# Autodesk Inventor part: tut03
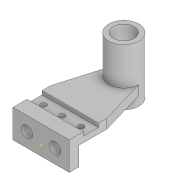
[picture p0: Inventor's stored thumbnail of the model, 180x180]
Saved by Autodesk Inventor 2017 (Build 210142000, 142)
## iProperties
Created: 2015-03
Part Number: tut03
Material: Generic
Document SubType Name: Modeling
Designer: Sandeep
Density: 1 g/cm^3
Appearance: Default
Author: Sandeep
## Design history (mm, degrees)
sketch "Sketch1"
  geometry: L1 (0, 0)-(10, 0); L2 (10, 0)-(10, 20); L3 (10, 20)-(40, 20); L4 (40, 20)-(40, 30); L5 (40, 30)-(31, 30); L6 (31, 30)-(31, 26); L7 (31, 26)-(15, 26); L8 (15, 26)-(15, 30); L9 (15, 30)-(0, 30); L10 (0, 30)-(0, 0)
  constraints: 20 end point, 7 perpendicular, 1 collinear, 1 horizontal, 1 parallel, 1 vertical
  dimensions: "d0" = 10 distance of L1.start L1.end; "d1" = 30 distance of L9.end L1.start; "d2" = 4 distance between parallel lines of L9 L7; "d3" = 15 distance of L8.end L9.end; "d4" = 16 distance of L6.end L7.end; "d5" = 40 distance between parallel lines of L4 L10; "d6" = 10 distance between parallel lines of L5 L3
extrude "Extrusion1" new body sketch "Sketch1" stored distance "d7" = 60; taper "d8" = 0 deg
sketch "Sketch2"
  geometry: L1 (0, 40)-(14, 88); L2 (14, 88)-(46, 88); L3 (0, 40)-(60, 40) reference; L4 (46, 88)-(60, 40); L5 (60, 40)-(0, 40); L6 (30, 0)-(30, 52.82)
  constraints: 11 end point, 1 horizontal, 1 vertical, 1 other
  dimensions: "d9" = 48 distance between parallel lines of L3 L2; "d10" = 32 distance of L1.end L2.end
extrude "Extrusion2" join sketch "Sketch2" distance "d11" = 10; taper "d12" = 0 deg
workplane "Work Plane1"
sketch "Sketch3"
  geometry: 1 further point
sketch "Sketch4"
  geometry: L1 (46, 78)-(14, 78) reference; C1 r 16 at (30, 78); 1 further point
  constraints: 1 centre point, 1 midpoint
  dimensions: "d14" = 32 diameter of C1
extrude "Extrusion3" join sketch "Sketch4" distance "d15" = 60; taper "d16" = 0 deg
sketch "Sketch5"
  geometry: C1 r 11 at (0, 0); C2 r 16 at (0, 0) reference; 1 further point
  constraints: 1 centre point, 1 concentric
  dimensions: "d17" = 22 diameter of C1
extrude "Extrusion4" cut sketch "Sketch5" stored distance "d18" = 0; taper "d19" = 0 deg
sketch "Sketch6"
  geometry: L1 (0.322, 7.5)-(90.552, 7.5); L2 (0, -15)-(60, -15) reference; L3 (0, 0)-(0, 16) reference; C1 r 3 at (10, 7.5); C2 r 3 at (30, 7.5); C3 r 3 at (50, 7.5); 1 further point
  constraints: 3 centre point, 3 point on line, 2 end point, 2 equal radius, 1 horizontal
  dimensions: "d20" = 22.5 distance between parallel lines of L2 L1; "d21" = 6 diameter of C1; "d22" = 10 distance from line of L3 C1.centre; "d23" = 20 distance of C2.centre C1.centre; "d24" = 20 distance of C3.centre C2.centre
extrude "Extrusion5" cut sketch "Sketch6" stored distance "d25" = 60; taper "d26" = 0 deg
sketch "Sketch7"
  geometry: L1 (0, 0)-(0, 30) reference; L2 (60, 30)-(60, 0) reference; L3 (60, 0)-(0, 0) reference; L4 (45, 15)-(-17, 15); C1 r 6 at (15, 15); C2 r 6 at (45, 15); 1 further point
  constraints: 2 centre point, 2 end point, 1 equal radius, 1 horizontal, 1 point on line
  dimensions: "d27" = 12 diameter of C2; "d28" = 30 distance of L4.start C1.centre; "d29" = 15 distance from line of L2 L4.start; "d32" = 15 distance from line of L4.start L3
extrude "Extrusion6" cut sketch "Sketch7" distance "d30" = 10; taper "d31" = 0 deg
body "Solid1"
